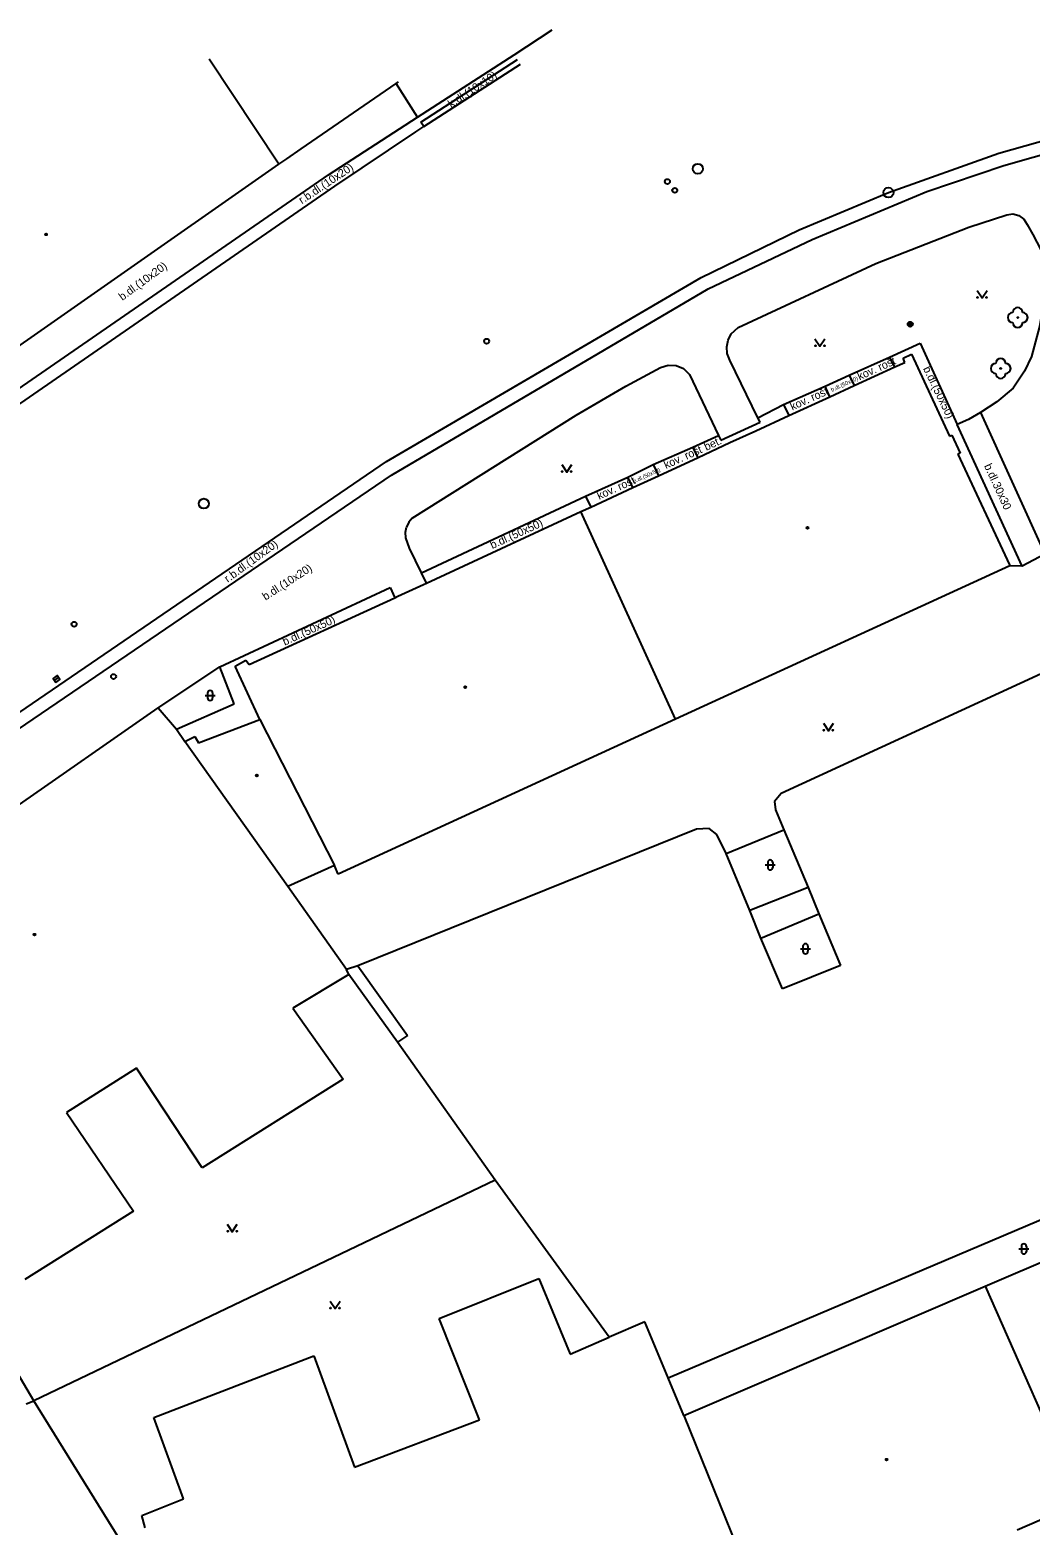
# Model space of a CAD drawing. Extents: x -599770 to -598493, y -1162076 to -1159209.
# Drawn here: x -599485.4 to -599435.5, y -1161177.8 to -1161103.1 of the extents above; entities that cross this region are included whole.
import ezdxf

# ---------------------------------------------------------------- set-up
doc = ezdxf.new("R2010")
doc.units = 0
doc.layers.add('Podklad', color=7, linetype='Continuous')

msp = doc.modelspace()

# ---------------------------------------------------------------- linework, layer by layer
at = {"layer": 'Podklad'}
for p, q in [((-599484.191, -1161135.603), (-599483.989, -1161135.457)), ((-599476.663, -1161136.358), (-599476.163, -1161136.358)), ((-599476.538, -1161136.233), (-599476.538, -1161136.483)), ((-599476.288, -1161136.233), (-599476.288, -1161136.483)), ((-599448.683, -1161144.828), (-599448.183, -1161144.828)), ((-599448.558, -1161144.703), (-599448.558, -1161144.953)), ((-599448.308, -1161144.703), (-599448.308, -1161144.953)), ((-599446.923, -1161149.018), (-599446.423, -1161149.018)), ((-599446.798, -1161148.893), (-599446.798, -1161149.143)), ((-599446.548, -1161148.893), (-599446.548, -1161149.143)), ((-599436.013, -1161164.018), (-599435.513, -1161164.018)), ((-599435.888, -1161163.893), (-599435.888, -1161164.143)), ((-599435.638, -1161163.893), (-599435.638, -1161164.143))]:
    msp.add_line(p, q, dxfattribs=at)
for points in [[(-599470.5, -1161110.34), (-599466.05, -1161107.45), (-599461.23, -1161104.33), (-599459.32, -1161103.09)], [(-599472.98, -1161109.8), (-599476.46, -1161104.55)], [(-599465.89, -1161107.7), (-599461.06, -1161104.57)], [(-599465.74, -1161107.92), (-599460.91, -1161104.8)], [(-599471.87, -1161109.03), (-599467.12, -1161105.77), (-599467.01, -1161105.69)], [(-599466.05, -1161107.45), (-599467.12, -1161105.77)], [(-599470.19, -1161110.9), (-599466.14, -1161108.19)], [(-599466.14, -1161108.19), (-599465.74, -1161107.92)], [(-599465.74, -1161107.92), (-599465.89, -1161107.7)], [(-599437.01, -1161109.25), (-599432.59, -1161108)], [(-599472.58, -1161109.54), (-599471.87, -1161109.03)], [(-599436.77, -1161109.87), (-599432.36, -1161108.62)], [(-599489.92, -1161121.64), (-599472.98, -1161109.8)], [(-599472.98, -1161109.8), (-599472.58, -1161109.54)], [(-599442.52, -1161111.22), (-599437.01, -1161109.25)], [(-599487.63, -1161122.16), (-599470.5, -1161110.34)], [(-599440.61, -1161111.17), (-599436.77, -1161109.87)], [(-599487.29, -1161122.72), (-599470.19, -1161110.9)], [(-599446.99, -1161113.09), (-599442.52, -1161111.22)], [(-599446.34, -1161113.57), (-599440.61, -1161111.17)], [(-599438.51, -1161112.95), (-599436.62, -1161112.33)], [(-599436.62, -1161112.33), (-599436.32, -1161112.29)], [(-599436.32, -1161112.29), (-599436.02, -1161112.37)], [(-599436.02, -1161112.37), (-599435.77, -1161112.55)], [(-599435.77, -1161112.55), (-599435.6, -1161112.81)], [(-599435.6, -1161112.81), (-599435.32, -1161113.31)], [(-599451.89, -1161115.46), (-599446.99, -1161113.09)], [(-599451.54, -1161116.03), (-599446.34, -1161113.57)], [(-599443.16, -1161114.77), (-599438.51, -1161112.95)], [(-599435.32, -1161113.31), (-599434.72, -1161114.46), (-599434.683, -1161115.481), (-599434.75, -1161116.45), (-599434.975, -1161117.92), (-599435.38, -1161119.41), (-599435.737, -1161120.155), (-599436.29, -1161121), (-599437.108, -1161121.679), (-599437.93, -1161122.22)], [(-599450.03, -1161117.96), (-599443.16, -1161114.77)], [(-599467.6, -1161124.67), (-599451.89, -1161115.46)], [(-599467.36, -1161125.34), (-599451.54, -1161116.03)], [(-599438.1, -1161116.115), (-599437.85, -1161116.49), (-599437.6, -1161116.115)], [(-599450.38, -1161118.28), (-599450.03, -1161117.96)], [(-599450.45, -1161119.59), (-599450.58, -1161119.27), (-599450.6, -1161118.93), (-599450.54, -1161118.59), (-599450.38, -1161118.28)], [(-599446.2, -1161118.525), (-599445.95, -1161118.9), (-599445.7, -1161118.525)], [(-599442.47, -1161119.45), (-599440.95, -1161118.75)], [(-599440.95, -1161118.75), (-599439.09, -1161122.82)], [(-599444.49, -1161120.35), (-599442.47, -1161119.45)], [(-599442.2, -1161119.93), (-599442.47, -1161119.45)], [(-599441.79, -1161119.5), (-599441.37, -1161119.3)], [(-599441.71, -1161119.71), (-599441.79, -1161119.5)], [(-599441.37, -1161119.3), (-599439.47, -1161123.4)], [(-599455.64, -1161120.89), (-599453.92, -1161119.97)], [(-599453.92, -1161119.97), (-599453.54, -1161119.84)], [(-599453.54, -1161119.84), (-599453.13, -1161119.86)], [(-599453.13, -1161119.86), (-599452.76, -1161120.02), (-599452.47, -1161120.31)], [(-599452.47, -1161120.31), (-599451.01, -1161123.37)], [(-599449.05, -1161122.48), (-599450.45, -1161119.59)], [(-599449.15, -1161123.13), (-599447.51, -1161122.37), (-599445.46, -1161121.43), (-599444.24, -1161120.87), (-599442.2, -1161119.93), (-599441.71, -1161119.71)], [(-599458.12, -1161122.34), (-599455.64, -1161120.89)], [(-599447.77, -1161121.82), (-599445.69, -1161120.9)], [(-599445.69, -1161120.9), (-599444.49, -1161120.35)], [(-599445.46, -1161121.43), (-599445.69, -1161120.9)], [(-599444.49, -1161120.35), (-599444.24, -1161120.87)], [(-599449.05, -1161122.48), (-599447.77, -1161121.82)], [(-599447.77, -1161121.82), (-599447.51, -1161122.37)], [(-599466.32, -1161127.5), (-599458.12, -1161122.34)], [(-599448.94, -1161122.7), (-599449.05, -1161122.48)], [(-599437.93, -1161122.22), (-599438.526, -1161122.558), (-599439.09, -1161122.82)], [(-599437.93, -1161122.22), (-599434.71, -1161129.29), (-599435.85, -1161129.9), (-599439.09, -1161122.82)], [(-599450.9, -1161123.6), (-599448.94, -1161122.7)], [(-599450.45, -1161123.72), (-599449.15, -1161123.13)], [(-599465.75, -1161130.81), (-599465.6, -1161130.74), (-599457.89, -1161127.17), (-599457.4, -1161126.94), (-599455.3, -1161125.97), (-599454.02, -1161125.38), (-599452.04, -1161124.46), (-599450.45, -1161123.72)], [(-599454.28, -1161124.82), (-599452.3, -1161123.95)], [(-599452.3, -1161123.95), (-599451.01, -1161123.37)], [(-599452.04, -1161124.46), (-599452.3, -1161123.95)], [(-599451.01, -1161123.37), (-599450.9, -1161123.6)], [(-599439.47, -1161123.4), (-599439.36, -1161123.35)], [(-599439.36, -1161123.35), (-599438.95, -1161124.24)], [(-599489.57, -1161139.67), (-599467.6, -1161124.67)], [(-599438.95, -1161124.24), (-599439.06, -1161124.29)], [(-599439.06, -1161124.29), (-599436.48, -1161129.83), (-599436.46, -1161129.87)], [(-599489.14, -1161140.17), (-599467.36, -1161125.34)], [(-599458.85, -1161124.815), (-599458.6, -1161125.19), (-599458.35, -1161124.815)], [(-599457.67, -1161126.4), (-599455.55, -1161125.44)], [(-599455.55, -1161125.44), (-599454.28, -1161124.82)], [(-599455.3, -1161125.97), (-599455.55, -1161125.44)], [(-599454.28, -1161124.82), (-599454.02, -1161125.38)], [(-599465.85, -1161130.23), (-599457.67, -1161126.4)], [(-599457.67, -1161126.4), (-599457.4, -1161126.94)], [(-599466.49, -1161127.7), (-599466.61, -1161127.94)], [(-599466.32, -1161127.5), (-599466.49, -1161127.7)], [(-599453.16, -1161137.55), (-599457.89, -1161127.17)], [(-599466.64, -1161128.47), (-599466.66, -1161128.2), (-599466.61, -1161127.94)], [(-599466.46, -1161128.99), (-599466.64, -1161128.47)], [(-599465.85, -1161130.23), (-599466.46, -1161128.99)], [(-599436.46, -1161129.87), (-599453.16, -1161137.55)], [(-599435.85, -1161129.9), (-599436.46, -1161129.87)], [(-599465.6, -1161130.74), (-599465.85, -1161130.23)], [(-599475.93, -1161134.92), (-599467.42, -1161130.96)], [(-599474.47, -1161134.81), (-599467.19, -1161131.47), (-599467.03, -1161131.4), (-599465.75, -1161130.81)], [(-599467.42, -1161130.96), (-599467.19, -1161131.47)], [(-599427.98, -1161132.09), (-599447.88, -1161141.26)], [(-599479.01, -1161136.98), (-599475.93, -1161134.92)], [(-599475.21, -1161136.78), (-599475.93, -1161134.92)], [(-599475.16, -1161134.89), (-599474.63, -1161134.6)], [(-599473.93, -1161137.56), (-599475.16, -1161134.89)], [(-599474.63, -1161134.6), (-599474.47, -1161134.81)], [(-599486.32, -1161142.08), (-599479.01, -1161136.98)], [(-599479.01, -1161136.98), (-599478.1, -1161138.04)], [(-599478.1, -1161138.04), (-599475.21, -1161136.78)], [(-599478.1, -1161138.04), (-599477.67, -1161138.65)], [(-599476.99, -1161138.72), (-599473.93, -1161137.56)], [(-599473.93, -1161137.56), (-599470.2, -1161144.85)], [(-599453.16, -1161137.55), (-599470.02, -1161145.29)], [(-599445.78, -1161137.745), (-599445.53, -1161138.12), (-599445.28, -1161137.745)], [(-599477.67, -1161138.65), (-599477.18, -1161138.41)], [(-599472.54, -1161145.91), (-599477.67, -1161138.65)], [(-599477.18, -1161138.41), (-599476.99, -1161138.72)], [(-599447.88, -1161141.26), (-599448.22, -1161141.65)], [(-599448.22, -1161141.65), (-599448.17, -1161142.07)], [(-599448.17, -1161142.07), (-599447.75, -1161143.07)], [(-599452.12, -1161143.04), (-599469.03, -1161149.87)], [(-599451.48, -1161143), (-599452.12, -1161143.04)], [(-599451.1, -1161143.3), (-599451.48, -1161143)], [(-599450.64, -1161144.26), (-599451.1, -1161143.3)], [(-599450.64, -1161144.26), (-599447.75, -1161143.07)], [(-599447.75, -1161143.07), (-599446.53, -1161145.95)], [(-599470.2, -1161144.85), (-599472.54, -1161145.91)], [(-599470.02, -1161145.29), (-599470.2, -1161144.85)], [(-599449.46, -1161147.11), (-599450.64, -1161144.26)], [(-599469.61, -1161150.05), (-599472.54, -1161145.91)], [(-599446.53, -1161145.95), (-599449.46, -1161147.11)], [(-599446.53, -1161145.95), (-599446, -1161147.28)], [(-599448.9, -1161148.48), (-599449.46, -1161147.11)], [(-599448.9, -1161148.48), (-599446, -1161147.28)], [(-599446, -1161147.28), (-599444.93, -1161149.85)], [(-599447.82, -1161151.02), (-599448.9, -1161148.48)], [(-599469.03, -1161149.87), (-599469.61, -1161150.05)], [(-599469.49, -1161150.31), (-599469.61, -1161150.05)], [(-599469.03, -1161149.87), (-599466.55, -1161153.35)], [(-599444.93, -1161149.85), (-599447.82, -1161151.02)], [(-599469.49, -1161150.31), (-599472.29, -1161151.98)], [(-599467.05, -1161153.69), (-599469.49, -1161150.31)], [(-599472.29, -1161151.98), (-599469.77, -1161155.54)], [(-599466.55, -1161153.35), (-599467.05, -1161153.69)], [(-599462.18, -1161160.59), (-599467.05, -1161153.69)], [(-599480.09, -1161154.98), (-599483.59, -1161157.2)], [(-599476.82, -1161159.97), (-599480.09, -1161154.98)], [(-599469.77, -1161155.54), (-599476.82, -1161159.97)], [(-599483.59, -1161157.2), (-599480.24, -1161162.14)], [(-599462.18, -1161160.59), (-599485.23, -1161171.61)], [(-599456.48, -1161168.43), (-599462.18, -1161160.59)], [(-599453.53, -1161170.47), (-599429.28, -1161160.16)], [(-599437.69, -1161165.89), (-599426.49, -1161161.09)], [(-599480.24, -1161162.14), (-599485.67, -1161165.55)], [(-599475.56, -1161162.785), (-599475.31, -1161163.16), (-599475.06, -1161162.785)], [(-599485.23, -1161171.61), (-599489.52, -1161164.34)], [(-599464.98, -1161167.5), (-599459.99, -1161165.5)], [(-599459.99, -1161165.5), (-599458.42, -1161169.28)], [(-599452.75, -1161172.35), (-599437.69, -1161165.89)], [(-599437.69, -1161165.89), (-599432.92, -1161176.71)], [(-599470.42, -1161166.625), (-599470.17, -1161167), (-599469.92, -1161166.625)], [(-599462.96, -1161172.56), (-599464.98, -1161167.5)], [(-599454.7, -1161167.67), (-599456.48, -1161168.43)], [(-599453.53, -1161170.47), (-599454.7, -1161167.67)], [(-599458.42, -1161169.28), (-599456.48, -1161168.43)], [(-599479.23, -1161172.45), (-599471.24, -1161169.36)], [(-599471.24, -1161169.36), (-599469.2, -1161174.93)], [(-599452.75, -1161172.35), (-599453.53, -1161170.47)], [(-599485.6, -1161171.77), (-599485.23, -1161171.61)], [(-599480.96, -1161178.49), (-599485.23, -1161171.61)], [(-599477.74, -1161176.51), (-599479.23, -1161172.45)], [(-599469.2, -1161174.93), (-599462.96, -1161172.56)], [(-599452.75, -1161172.35), (-599448.3, -1161183.35)], [(-599479.83, -1161177.34), (-599477.74, -1161176.51)], [(-599433.37, -1161176.9), (-599436.1, -1161178.08)], [(-599479.66, -1161177.97), (-599479.83, -1161177.34)]]:
    msp.add_lwpolyline(points, dxfattribs=at)
msp.add_lwpolyline([(-599484.118, -1161135.704), (-599483.916, -1161135.558), (-599484.062, -1161135.356), (-599484.264, -1161135.502)], close=True, dxfattribs=at)
for centre, radius in [((-599452.05, -1161110.03), 0.25), ((-599453.57, -1161110.67), 0.125), ((-599453.2, -1161111.11), 0.125), ((-599442.53, -1161111.22), 0.25), ((-599484.61, -1161113.31), 0.045), ((-599484.61, -1161113.31), 0.0199), ((-599438.075, -1161116.465), 0.025), ((-599437.625, -1161116.465), 0.025), ((-599441.44, -1161117.8), 0.125), ((-599441.44, -1161117.8), 0.1), ((-599441.44, -1161117.8), 0.075), ((-599441.44, -1161117.8), 0.05), ((-599441.44, -1161117.8), 0.025), ((-599436.07, -1161117.47), 0.025), ((-599462.6, -1161118.65), 0.125), ((-599446.175, -1161118.875), 0.025), ((-599445.725, -1161118.875), 0.025), ((-599436.92, -1161120.01), 0.025), ((-599458.825, -1161125.165), 0.025), ((-599458.375, -1161125.165), 0.025), ((-599476.73, -1161126.77), 0.25), ((-599446.57, -1161127.98), 0.045), ((-599446.57, -1161127.98), 0.0199), ((-599483.21, -1161132.8), 0.125), ((-599481.24, -1161135.41), 0.125), ((-599463.67, -1161135.94), 0.045), ((-599463.67, -1161135.94), 0.0199), ((-599445.755, -1161138.095), 0.025), ((-599445.305, -1161138.095), 0.025), ((-599474.08, -1161140.36), 0.045), ((-599474.08, -1161140.36), 0.0199), ((-599485.19, -1161148.31), 0.045), ((-599485.19, -1161148.31), 0.0199), ((-599475.535, -1161163.135), 0.025), ((-599475.085, -1161163.135), 0.025), ((-599470.395, -1161166.975), 0.025), ((-599469.945, -1161166.975), 0.025), ((-599442.62, -1161174.55), 0.045), ((-599442.62, -1161174.55), 0.0199)]:
    msp.add_circle(centre, radius, dxfattribs=at)
for centre, radius, start, end in [((-599436.32, -1161117.47), 0.25, 90, 270), ((-599436.07, -1161117.22), 0.25, 0, 180), ((-599435.82, -1161117.47), 0.25, 270, 90), ((-599436.07, -1161117.72), 0.25, 180, 0), ((-599436.92, -1161119.76), 0.25, 0, 180), ((-599437.17, -1161120.01), 0.25, 90, 270), ((-599436.92, -1161120.26), 0.25, 180, 0), ((-599436.67, -1161120.01), 0.25, 270, 90), ((-599476.413, -1161136.233), 0.125, 0, 180), ((-599476.413, -1161136.483), 0.125, 180, 0), ((-599448.433, -1161144.703), 0.125, 0, 180), ((-599448.433, -1161144.953), 0.125, 180, 0), ((-599446.673, -1161148.893), 0.125, 0, 180), ((-599446.673, -1161149.143), 0.125, 180, 0), ((-599435.763, -1161163.893), 0.125, 0, 180), ((-599435.763, -1161164.143), 0.125, 180, 0)]:
    msp.add_arc(centre, radius, start, end, dxfattribs=at)

# ---------------------------------------------------------------- texts
for s, height, rotation, p in [('k.dl.(10x10)', 0.4, 33.6044, (-599464.37, -1161107)), ('r.b.dl.(10x20)', 0.4, 33.81376, (-599471.83, -1161111.81)), ('b.dl.(10x20)', 0.4, 36.20645, (-599480.8, -1161116.64)), ('kov. rošt', 0.4, 24.31304, (-599443.97, -1161120.61)), ('b.dl.(50x50)', 0.4, 295.84918, (-599440.81, -1161120.02)), ('kov. rošt', 0.4, 24.31304, (-599447.33, -1161122.12)), ('b.dl.(50x50)', 0.2, 24.31304, (-599445.35, -1161121.18)), ('kov. rošt', 0.4, 24.31304, (-599453.64, -1161125.04)), ('bet.', 0.4, 24.31304, (-599451.63, -1161124.13)), ('b.dl.30x30', 0.4, 294.74599, (-599437.76, -1161124.88)), ('kov. rošt', 0.4, 24.31304, (-599456.98, -1161126.58)), ('b.dl.(50x50)', 0.2, 24.31304, (-599455.23, -1161125.75)), ('b.dl.(50x50)', 0.4, 24.31304, (-599462.32, -1161129.04)), ('r.b.dl.(10x20)', 0.4, 36.20645, (-599475.53, -1161130.73)), ('b.dl.(10x20)', 0.4, 32.74577, (-599473.65, -1161131.62)), ('b.dl.(50x50)', 0.4, 24.31304, (-599472.69, -1161133.87))]:
    msp.add_text(s, height=height, rotation=rotation, dxfattribs=at).set_placement(p)

doc.saveas('drawing.dxf')
